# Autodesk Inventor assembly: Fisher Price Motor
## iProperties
Company: Cybersonics
Created: 2007-01
Document SubType Name: Assembly
Description: Fisher Price Motor w/ 16:1 Transmission
Title: Fisher Price Motor
